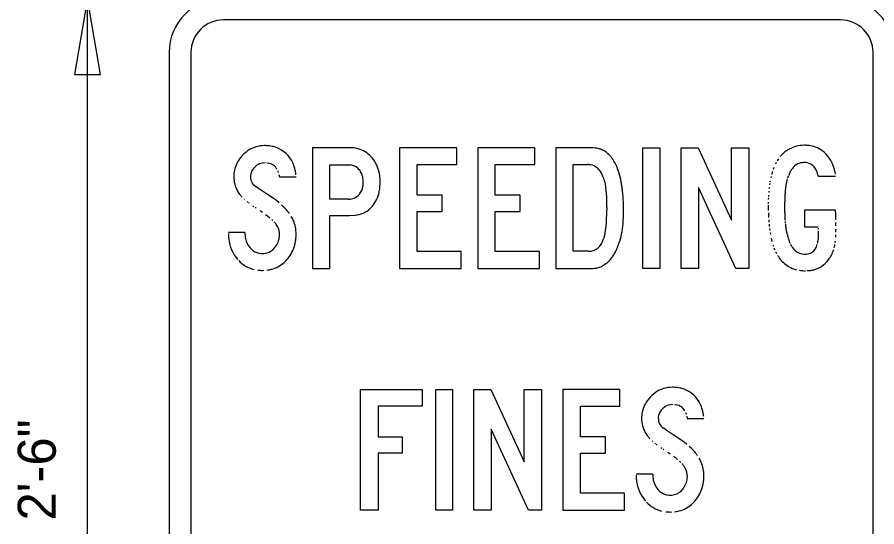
# Model space of a CAD drawing. Extents: x 0 to 770, y 0 to 495.
# Drawn here: x 242 to 321.1, y 84.8 to 131.8 of the extents above; entities that cross this region are included whole.
import ezdxf

# ---------------------------------------------------------------- set-up
doc = ezdxf.new("R2010")
doc.units = 0
for name, color, linetype in [('Default', 7, 'Continuous'), ('Dimension', 7, 'Continuous'), ('GSBWFill', 7, 'Continuous'), ('GSDims', 7, 'Continuous'), ('TextStructures', 7, 'Continuous')]:
    doc.layers.add(name, color=color, linetype=linetype)

msp = doc.modelspace()

# ---------------------------------------------------------------- linework, layer by layer
at = {"layer": 'Default'}
for p, q in [((269.223, 119.747), (269.223, 108.62)), ((273.034, 119.722), (273.034, 119.721)), ((273.42, 119.643), (273.42, 119.644)), ((282.487, 119.747), (277.234, 119.747)), ((277.234, 119.747), (277.234, 108.62)), ((282.487, 118.19), (282.487, 119.747)), ((289.675, 119.747), (284.423, 119.747)), ((284.423, 119.747), (284.423, 108.62)), ((289.675, 118.19), (289.675, 119.747)), ((294.627, 119.747), (291.612, 119.747)), ((291.612, 119.747), (291.612, 108.62)), ((295.67, 119.622), (295.67, 119.622)), ((295.969, 119.498), (295.969, 119.498)), ((299.623, 119.747), (301.181, 119.747)), ((299.623, 108.62), (299.623, 119.747)), ((301.181, 119.747), (301.181, 108.62)), ((303.14, 108.62), (303.14, 119.747)), ((303.14, 119.747), (304.709, 119.747)), ((304.709, 119.747), (307.769, 113.071)), ((307.769, 113.071), (307.769, 119.747)), ((307.769, 119.747), (309.371, 119.747)), ((309.371, 119.747), (309.371, 108.62)), ((274.608, 118.914), (274.608, 118.914)), ((296.485, 119.113), (296.485, 119.113)), ((296.692, 118.885), (296.692, 118.885)), ((296.953, 118.511), (296.845, 118.679)), ((265, 118.34), (265.142, 118.323)), ((270.814, 115.018), (270.814, 118.178)), ((270.814, 118.178), (272.427, 118.178)), ((272.427, 118.178), (272.706, 118.16)), ((278.848, 115.385), (278.848, 118.19)), ((278.848, 118.19), (282.487, 118.19)), ((286.037, 115.385), (286.037, 118.19)), ((286.037, 118.19), (289.675, 118.19)), ((293.203, 110.211), (293.203, 118.19)), ((293.203, 118.19), (294.516, 118.19)), ((294.516, 118.19), (294.516, 118.19)), ((294.666, 118.183), (294.666, 118.183)), ((295.258, 117.995), (295.258, 117.995)), ((297.054, 118.33), (297.054, 118.33)), ((297.119, 118.203), (297.119, 118.203)), ((297.18, 118.071), (297.18, 118.071)), ((297.239, 117.934), (297.239, 117.934)), ((266.012, 117.619), (266.072, 117.455)), ((266.126, 117.27), (266.174, 117.066)), ((266.174, 117.066), (267.709, 117.066)), ((273.523, 117.722), (273.523, 117.722)), ((273.744, 117.341), (273.744, 117.341)), ((275.324, 117.602), (275.324, 117.602)), ((275.39, 117.29), (275.39, 117.29)), ((295.577, 117.724), (295.577, 117.724)), ((295.714, 117.546), (295.714, 117.546)), ((295.797, 117.411), (295.797, 117.411)), ((295.872, 117.262), (295.873, 117.262)), ((295.942, 117.102), (295.942, 117.102)), ((297.349, 117.643), (297.295, 117.791)), ((297.399, 117.49), (297.399, 117.49)), ((297.447, 117.331), (297.447, 117.331)), ((311.412, 117.086), (311.389, 116.985)), ((312.981, 117.053), (313.011, 117.143)), ((315.748, 117.121), (317.35, 117.121)), ((315.748, 117.121), (315.748, 117.121)), ((317.295, 117.497), (317.256, 117.676)), ((317.326, 117.312), (317.295, 117.497)), ((273.834, 117.043), (273.834, 117.043)), ((273.885, 116.532), (273.885, 116.532)), ((275.4, 115.946), (275.443, 116.621)), ((275.43, 116.963), (275.43, 116.963)), ((296.153, 116.314), (296.172, 116.19)), ((311.29, 116.451), (311.273, 116.339)), ((311.326, 116.67), (311.307, 116.561)), ((312.785, 116.105), (312.837, 116.459)), ((312.837, 116.459), (312.899, 116.765)), ((312.899, 116.765), (312.924, 116.865)), ((312.952, 116.961), (312.981, 117.053)), ((264.237, 115.997), (264.012, 116.17)), ((264.435, 115.856), (264.237, 115.997)), ((264.605, 115.742), (264.435, 115.856)), ((264.973, 115.512), (264.605, 115.742)), ((265.311, 115.291), (264.973, 115.512)), ((273.856, 116.186), (273.856, 116.186)), ((275.225, 115.208), (275.311, 115.489)), ((296.172, 116.19), (296.19, 116.059)), ((296.222, 115.775), (296.235, 115.622)), ((308.158, 108.62), (304.731, 116.075)), ((304.731, 116.075), (304.731, 108.62)), ((311.205, 115.751), (311.195, 115.628)), ((311.243, 116.109), (311.229, 115.991)), ((312.719, 115.368), (312.743, 115.703)), ((312.743, 115.703), (312.785, 116.105)), ((262.93, 115.001), (262.974, 114.964)), ((263.192, 114.793), (263.257, 114.745)), ((263.327, 114.693), (263.4, 114.64)), ((265.619, 115.078), (265.311, 115.291)), ((265.895, 114.874), (265.619, 115.078)), ((266.143, 114.678), (265.895, 114.874)), ((273.042, 115.108), (273.042, 115.108)), ((273.529, 115.474), (273.529, 115.474)), ((274.838, 114.478), (275.118, 114.946)), ((281.151, 115.385), (278.848, 115.385)), ((281.151, 113.872), (281.151, 115.385)), ((288.34, 115.385), (286.037, 115.385)), ((288.34, 113.872), (288.34, 115.385)), ((296.257, 115.294), (296.265, 115.12)), ((296.278, 114.749), (296.282, 114.553)), ((297.802, 115.128), (297.794, 115.239)), ((297.821, 114.789), (297.815, 114.904)), ((311.154, 114.716), (311.152, 114.579)), ((311.165, 115.118), (311.16, 114.986)), ((311.178, 115.376), (311.171, 115.248)), ((312.691, 114.614), (312.701, 115.006)), ((312.701, 115.006), (312.719, 115.368)), ((263.737, 114.401), (263.832, 114.335)), ((263.932, 114.266), (264.035, 114.196)), ((264.371, 113.969), (264.491, 113.888)), ((266.555, 114.316), (266.363, 114.492)), ((296.282, 114.553), (296.284, 114.35)), ((311.152, 114.44), (311.153, 114.204)), ((311.153, 114.204), (311.157, 113.974)), ((312.687, 114.195), (312.691, 114.614)), ((312.688, 114.092), (312.687, 114.195)), ((312.689, 113.99), (312.688, 114.092)), ((312.69, 113.889), (312.689, 113.99)), ((317.35, 114.006), (314.501, 114.006)), ((314.501, 114.006), (314.501, 112.448)), ((317.364, 113.671), (317.35, 114.006)), ((264.491, 113.888), (264.616, 113.805)), ((264.905, 113.594), (265.083, 113.458)), ((265.083, 113.458), (265.283, 113.293)), ((265.467, 113.143), (265.577, 113.039)), ((270.814, 108.62), (270.814, 113.494)), ((270.814, 113.494), (272.612, 113.494)), ((272.612, 113.494), (273.172, 113.533)), ((273.43, 113.581), (273.43, 113.581)), ((273.79, 113.691), (273.79, 113.691)), ((278.848, 110.2), (278.848, 113.872)), ((278.848, 113.872), (281.151, 113.872)), ((286.037, 110.2), (286.037, 113.872)), ((286.037, 113.872), (288.34, 113.872)), ((296.268, 113.577), (296.25, 113.253)), ((296.281, 113.871), (296.268, 113.577)), ((297.816, 113.024), (297.831, 113.286)), ((297.831, 113.286), (297.84, 113.554)), ((297.84, 113.554), (297.843, 113.828)), ((311.162, 113.749), (311.171, 113.529)), ((311.171, 113.529), (311.181, 113.314)), ((312.692, 113.79), (312.69, 113.889)), ((312.694, 113.692), (312.692, 113.79)), ((312.697, 113.595), (312.694, 113.692)), ((312.7, 113.5), (312.697, 113.595)), ((312.704, 113.406), (312.7, 113.5)), ((312.709, 113.313), (312.704, 113.406)), ((312.714, 113.221), (312.709, 113.313)), ((312.72, 113.131), (312.714, 113.221)), ((312.726, 113.042), (312.72, 113.131)), ((317.375, 113.369), (317.364, 113.671)), ((317.381, 113.098), (317.375, 113.369)), ((296.196, 112.504), (296.155, 112.156)), ((297.737, 112.272), (297.769, 112.517)), ((311.194, 113.103), (311.21, 112.898)), ((311.228, 112.697), (311.248, 112.501)), ((312.739, 112.867), (312.732, 112.954)), ((312.747, 112.782), (312.739, 112.867)), ((312.764, 112.615), (312.756, 112.698)), ((312.774, 112.533), (312.764, 112.615)), ((312.784, 112.453), (312.774, 112.533)), ((312.794, 112.374), (312.784, 112.453)), ((312.805, 112.296), (312.794, 112.374)), ((314.501, 112.448), (315.748, 112.448)), ((315.756, 112.342), (315.759, 112.247)), ((317.382, 112.542), (317.383, 112.859)), ((263.002, 111.936), (261.478, 111.936)), ((261.478, 111.836), (261.48, 111.673)), ((263.002, 111.936), (263.002, 111.936)), ((296.051, 111.576), (295.988, 111.342)), ((296.107, 111.847), (296.051, 111.576)), ((296.155, 112.156), (296.107, 111.847)), ((297.548, 111.351), (297.604, 111.573)), ((297.604, 111.573), (297.654, 111.8)), ((297.654, 111.8), (297.698, 112.033)), ((297.698, 112.033), (297.737, 112.272)), ((311.27, 112.31), (311.295, 112.124)), ((311.323, 111.943), (311.352, 111.767)), ((312.816, 112.22), (312.805, 112.296)), ((312.828, 112.144), (312.816, 112.22)), ((312.841, 112.07), (312.828, 112.144)), ((312.854, 111.998), (312.841, 112.07)), ((312.867, 111.926), (312.854, 111.998)), ((312.882, 111.856), (312.867, 111.926)), ((312.896, 111.787), (312.882, 111.856)), ((312.911, 111.72), (312.896, 111.787)), ((315.744, 111.536), (315.732, 111.377)), ((315.752, 111.707), (315.744, 111.536)), ((315.757, 111.888), (315.752, 111.707)), ((315.759, 112.08), (315.757, 111.888)), ((317.356, 111.507), (317.366, 111.731)), ((317.373, 111.977), (317.379, 112.248)), ((295.781, 110.874), (295.781, 110.874)), ((295.875, 111.05), (295.875, 111.05)), ((297.418, 110.925), (297.418, 110.925)), ((311.419, 111.429), (311.455, 111.268)), ((311.455, 111.268), (311.495, 111.111)), ((311.58, 110.812), (311.626, 110.671)), ((315.699, 111.092), (315.677, 110.967)), ((315.717, 111.229), (315.699, 111.092)), ((315.732, 111.377), (315.717, 111.229)), ((317.272, 110.734), (317.293, 110.843)), ((317.312, 110.975), (317.329, 111.13)), ((282.91, 110.2), (278.848, 110.2)), ((282.91, 108.62), (282.91, 110.2)), ((290.098, 110.2), (286.037, 110.2)), ((290.098, 108.62), (290.098, 110.2)), ((294.949, 110.252), (294.949, 110.252)), ((296.983, 109.955), (296.983, 109.955)), ((297.081, 110.133), (297.081, 110.133)), ((297.22, 110.421), (297.22, 110.421)), ((317.226, 110.543), (317.272, 110.734)), ((296.477, 109.292), (296.477, 109.292)), ((296.657, 109.488), (296.77, 109.633)), ((296.879, 109.789), (296.879, 109.789)), ((264.605, 108.453), (264.743, 108.455)), ((269.223, 108.62), (270.814, 108.62)), ((277.234, 108.62), (282.91, 108.62)), ((284.423, 108.62), (290.098, 108.62)), ((296.221, 109.07), (296.221, 109.07)), ((301.181, 108.62), (299.623, 108.62)), ((304.731, 108.62), (303.14, 108.62)), ((309.371, 108.62), (308.158, 108.62)), ((273.629, 97.492), (279.304, 97.492)), ((273.629, 86.364), (273.629, 97.492)), ((279.304, 97.492), (279.304, 95.934)), ((280.551, 97.492), (282.108, 97.492)), ((280.551, 86.364), (280.551, 97.492)), ((282.108, 97.492), (282.108, 86.364)), ((284.067, 86.364), (284.067, 97.492)), ((284.067, 97.492), (285.636, 97.492)), ((285.636, 97.492), (288.696, 90.815)), ((288.696, 90.815), (288.696, 97.492)), ((288.696, 97.492), (290.298, 97.492)), ((290.298, 97.492), (290.298, 86.364)), ((297.509, 97.492), (292.257, 97.492)), ((292.257, 97.492), (292.257, 86.364)), ((297.509, 95.934), (297.509, 97.492)), ((279.304, 95.934), (275.254, 95.934)), ((275.254, 95.934), (275.254, 93.13)), ((293.87, 93.13), (293.87, 95.934)), ((293.87, 95.934), (297.509, 95.934)), ((302.523, 96.084), (302.665, 96.068)), ((303.535, 95.364), (303.595, 95.2)), ((303.649, 95.015), (303.696, 94.81)), ((303.696, 94.81), (305.232, 94.81)), ((289.086, 86.364), (285.658, 93.82)), ((285.658, 93.82), (285.658, 86.364)), ((301.76, 93.742), (301.535, 93.914)), ((301.958, 93.6), (301.76, 93.742)), ((302.127, 93.486), (301.958, 93.6)), ((302.496, 93.257), (302.127, 93.486)), ((275.254, 93.13), (277.468, 93.13)), ((277.468, 93.13), (277.468, 91.617)), ((296.174, 93.13), (293.87, 93.13)), ((296.174, 91.617), (296.174, 93.13)), ((300.453, 92.746), (300.497, 92.709)), ((302.834, 93.035), (302.496, 93.257)), ((303.141, 92.823), (302.834, 93.035)), ((303.418, 92.618), (303.141, 92.823)), ((303.666, 92.423), (303.418, 92.618)), ((300.715, 92.538), (300.78, 92.489)), ((300.849, 92.438), (300.923, 92.384)), ((301.26, 92.145), (301.355, 92.079)), ((301.454, 92.011), (301.557, 91.94)), ((304.077, 92.061), (303.885, 92.237)), ((277.468, 91.617), (275.254, 91.617)), ((275.254, 91.617), (275.254, 86.364)), ((293.87, 87.944), (293.87, 91.617)), ((293.87, 91.617), (296.174, 91.617)), ((301.893, 91.713), (302.014, 91.633)), ((302.014, 91.633), (302.138, 91.55)), ((302.428, 91.338), (302.606, 91.202)), ((302.606, 91.202), (302.806, 91.038)), ((302.99, 90.888), (303.099, 90.783)), ((300.525, 89.68), (299, 89.68)), ((299, 89.58), (299.003, 89.418)), ((300.525, 89.68), (300.525, 89.68)), ((297.932, 87.944), (293.87, 87.944)), ((297.932, 86.364), (297.932, 87.944)), ((275.254, 86.364), (273.629, 86.364)), ((282.108, 86.364), (280.551, 86.364)), ((285.658, 86.364), (284.067, 86.364)), ((290.298, 86.364), (289.086, 86.364)), ((292.257, 86.364), (297.932, 86.364)), ((302.127, 86.197), (302.266, 86.2))]:
    msp.add_line(p, q, dxfattribs=at)
for points in [[(272.621, 119.747), (272.621, 119.747), (269.223, 119.747)], [(295.025, 119.734), (294.832, 119.744), (294.627, 119.747)], [(295.373, 119.692), (295.205, 119.716), (295.025, 119.734)], [(295.67, 119.622), (295.528, 119.66), (295.373, 119.692)], [(297.535, 116.998), (297.514, 117.084), (297.493, 117.168)], [(296.033, 116.836), (296.033, 116.836), (296.06, 116.741)], [(296.06, 116.741), (296.085, 116.643), (296.109, 116.54)], [(296.109, 116.54), (296.132, 116.431), (296.153, 116.314)], [(297.575, 116.824), (297.555, 116.912), (297.535, 116.998)], [(297.629, 116.552), (297.612, 116.644), (297.575, 116.824)], [(297.662, 116.365), (297.646, 116.459), (297.629, 116.552)], [(297.692, 116.172), (297.677, 116.269), (297.662, 116.365)], [(296.19, 116.059), (296.207, 115.92), (296.222, 115.775)], [(296.235, 115.622), (296.247, 115.462), (296.257, 115.294)], [(297.72, 115.974), (297.706, 116.074), (297.692, 116.172)], [(297.744, 115.77), (297.732, 115.873), (297.72, 115.974)], [(297.766, 115.562), (297.755, 115.667), (297.744, 115.77)], [(297.794, 115.239), (297.785, 115.348), (297.766, 115.562)], [(272.539, 115.018), (272.539, 115.018), (270.814, 115.018)], [(296.265, 115.12), (296.273, 114.938), (296.278, 114.749)], [(297.815, 114.904), (297.809, 115.017), (297.802, 115.128)], [(297.831, 114.557), (297.826, 114.674), (297.821, 114.789)], [(296.284, 114.35), (296.285, 114.139), (296.281, 113.871)], [(297.837, 114.319), (297.834, 114.438), (297.831, 114.557)], [(297.842, 114.076), (297.84, 114.198), (297.837, 114.319)], [(297.843, 113.828), (297.843, 113.952), (297.842, 114.076)], [(296.25, 113.253), (296.23, 112.893), (296.196, 112.504)], [(297.769, 112.517), (297.796, 112.767), (297.816, 113.024)], [(297.418, 110.925), (297.486, 111.135), (297.548, 111.351)], [(294.571, 110.211), (294.571, 110.211), (293.203, 110.211)], [(291.612, 108.62), (294.827, 108.62), (295.002, 108.625)]]:
    msp.add_lwpolyline(points, dxfattribs=at)
for centre, radius, start, end in [((265.123, 116.823), 3.23, 125.4418, 141.2252), ((264.771, 117.297), 2.64, 89.2737, 125.1802), ((264.81, 116.188), 3.748, 83.339, 90.0746), ((264.87, 116.751), 3.182, 78.2121, 83.2376), ((264.941, 117.089), 2.837, 70.1046, 78.2264), ((264.992, 117.29), 2.63, 24.1049, 69.6601), ((272.625, 116.52), 3.227, 82.7267, 90.0706), ((272.678, 116.961), 2.784, 74.5351, 82.6474), ((272.74, 117.204), 2.532, 42.4587, 74.4236), ((295.229, 118.143), 1.544, 61.363, 73.3883), ((294.842, 117.45), 2.337, 45.3467, 61.1731), ((314.219, 117.347), 2.525, 121.8461, 132.9879), ((314.684, 116.681), 3.337, 115.972, 122.5995), ((314.512, 117.035), 2.943, 105.1938, 115.983), ((314.454, 117.227), 2.743, 89.949, 105.0722), ((314.461, 116.569), 3.401, 82.5188, 90.0791), ((314.517, 117.032), 2.935, 76.8308, 82.4098), ((314.594, 117.343), 2.615, 61.861, 76.9248), ((314.572, 117.331), 2.635, 43.5425, 61.5587), ((264.727, 117.101), 2.747, 140.5703, 168.2275), ((272.393, 116.855), 3.024, 14.2957, 42.9079), ((294.587, 117.181), 2.708, 39.0029, 45.5205), ((294.297, 116.943), 3.083, 34.2627, 39.0379), ((314.908, 116.772), 3.426, 145.0163, 149.0349), ((314.398, 117.158), 2.786, 133.0243, 140.7189), ((314.348, 117.111), 2.95, 24.4959, 43.6518), ((264.723, 117.076), 1.211, 132.6297, 202.1565), ((264.816, 117.056), 1.29, 88.5422, 135.0606), ((265.028, 117.302), 1.028, 26.6666, 83.6019), ((264.541, 117.036), 3.147, 16.2411, 24.9806), ((264.088, 116.898), 3.62, 11.0316, 16.3233), ((272.589, 116.96), 1.206, 39.2074, 84.4146), ((294.517, 116.47), 1.72, 85.0409, 90.052), ((294.566, 116.842), 1.345, 59.0008, 85.7331), ((294.538, 116.822), 1.376, 40.9656, 58.4431), ((293.693, 116.554), 3.801, 27.8491, 30.9695), ((293.355, 116.374), 4.184, 25.9265, 27.8738), ((293.066, 116.233), 4.506, 24.0732, 25.9267), ((292.744, 116.089), 4.859, 22.3109, 24.0735), ((292.388, 115.943), 5.244, 20.636, 22.3112), ((316.462, 116.022), 5.155, 158.4219, 160.466), ((315.428, 116.475), 4.025, 151.5644, 153.975), ((314.739, 116.776), 1.731, 138.496, 145.831), ((314.43, 117.076), 1.301, 106.6757, 139.3493), ((314.458, 116.934), 1.445, 89.5988, 106.1115), ((314.47, 116.846), 1.533, 84.3521, 90.0781), ((314.533, 117.267), 1.107, 53.1586, 85.4356), ((314.486, 117.233), 1.163, 35.156, 52.3499), ((314.201, 117.029), 1.514, 26.6079, 35.2343), ((314, 116.942), 3.336, 18.7846, 24.6542), ((313.634, 116.818), 3.723, 13.3229, 18.7785), ((264.916, 117.074), 2.938, 168.4628, 180.1612), ((264.6, 117.043), 2.622, 179.5181, 209.0783), ((263.592, 116.802), 4.125, 6.1794, 11.0296), ((272.311, 116.767), 1.543, 21.8218, 38.2319), ((272.057, 116.666), 1.817, 11.9834, 21.8077), ((271.947, 116.722), 3.49, 9.3702, 14.6018), ((271.582, 116.662), 3.859, 4.4743, 9.366), ((294.28, 116.591), 1.723, 33.6642, 41.1482), ((294.04, 116.43), 2.011, 29.1747, 33.6892), ((293.763, 116.275), 2.329, 25.0813, 29.1759), ((293.412, 116.111), 2.717, 21.3891, 25.0837), ((292.813, 115.881), 3.358, 16.5148, 21.3058), ((291.566, 115.647), 6.118, 17.5334, 19.0451), ((291.097, 115.499), 6.61, 16.0981, 17.5338), ((290.587, 115.351), 7.14, 14.7347, 16.0984), ((317.558, 115.661), 6.309, 162.4213, 165.0947), ((316.111, 116.056), 3.285, 157.4853, 160.6635), ((315.668, 116.239), 2.806, 153.9576, 157.4883), ((315.307, 116.416), 2.404, 150.0465, 153.9602), ((315.02, 116.581), 2.073, 145.7282, 150.0482), ((313.901, 116.878), 1.85, 21.5964, 26.6481), ((313.548, 116.738), 2.229, 17.1396, 21.6006), ((312.921, 116.551), 2.884, 11.4154, 17.022), ((264.486, 117.013), 0.968, 204.0171, 240.6614), ((271.4, 116.543), 2.485, 359.7377, 11.6141), ((271.909, 116.524), 1.976, 350.1569, 0.216), ((271.098, 116.624), 4.345, 359.9525, 4.4725), ((264.813, 117.169), 2.869, 209.1955, 217.4851), ((272.396, 116.426), 1.48, 319.9774, 350.6811), ((271.491, 116.468), 3.943, 345.6252, 352.3887), ((265.079, 117.371), 3.203, 217.4723, 222.6179), ((272.557, 116.368), 1.35, 269.234, 291.0673), ((272.605, 116.196), 1.172, 291.8743, 321.9947), ((272.423, 116.204), 2.973, 334.9699, 340.4326), ((263.436, 111.073), 4.5, 39.1273, 46.1255), ((263.807, 111.376), 4.021, 34.7564, 39.1072), ((272.97, 115.874), 2.332, 290.5966, 323.2356), ((264.338, 111.716), 3.389, 22.8402, 30.1431), ((272.715, 116.662), 3.163, 278.3016, 283.0626), ((272.816, 116.246), 2.735, 282.9803, 290.8726), ((264.219, 111.495), 2.048, 35.3865, 43.879), ((264.627, 111.767), 1.558, 5.1973, 35.9416), ((264.539, 111.803), 3.17, 359.7757, 22.7948), ((265.574, 111.822), 4.096, 182.078, 186.51), ((265.512, 111.89), 2.51, 178.9652, 191.6289), ((264.326, 111.733), 1.856, 320.6387, 355.8508), ((264.301, 111.757), 1.884, 355.1863, 4.6054), ((263.389, 111.787), 4.32, 353.6698, 0.0575), ((318.287, 112.958), 5.516, 192.9693, 195.0608), ((264.879, 111.71), 3.393, 185.9642, 221.4144), ((264.955, 111.778), 1.942, 191.6865, 220.534), ((264.228, 111.672), 3.473, 341.545, 348.9423), ((263.914, 111.734), 3.793, 348.9338, 353.5913), ((294.655, 111.513), 1.295, 283.1391, 330.4047), ((294.144, 111.866), 1.914, 328.766, 334.7522), ((293.958, 111.959), 2.122, 334.6275, 343.0977), ((291.622, 112.905), 6.125, 336.0791, 341.1452), ((317.628, 112.782), 4.834, 195.083, 196.6096), ((317.186, 112.651), 4.373, 196.6088, 198.2409), ((316.786, 112.519), 3.952, 198.2401, 199.9862), ((316.426, 112.388), 3.569, 199.9854, 201.8543), ((316.104, 112.259), 3.222, 201.8535, 203.8541), ((315.528, 111.99), 2.586, 205.9842, 209.4497), ((314.291, 111.162), 1.396, 334.8823, 347.1516), ((264.632, 111.496), 1.514, 220.3788, 233.6082), ((264.551, 111.407), 1.394, 234.108, 267.0901), ((264.604, 111.679), 1.669, 265.7463, 283.9893), ((264.651, 111.423), 1.41, 284.674, 322.0204), ((264.481, 111.589), 3.206, 317.9943, 341.5213), ((294.582, 111.859), 1.649, 269.6389, 282.8773), ((293.66, 111.905), 3.853, 326.6728, 329.5939), ((293.286, 112.125), 4.287, 329.5932, 332.3136), ((292.684, 112.436), 4.964, 332.3586, 336.0481), ((316.345, 112.302), 4.994, 200.7366, 203.0596), ((315.611, 111.971), 4.188, 205.5245, 208.1364), ((315.217, 111.815), 2.229, 209.4776, 213.304), ((314.922, 111.621), 1.877, 213.2805, 219.0188), ((314.681, 111.425), 1.565, 219.0003, 227.0806), ((314.457, 111.172), 1.228, 226.6802, 271.0039), ((314.485, 111.608), 1.664, 269.8001, 279.9547), ((314.559, 111.16), 1.21, 280.1681, 292.7446), ((314.629, 110.971), 1.009, 293.1983, 336.5465), ((313.889, 111.402), 3.444, 333.3488, 342.4003), ((264.478, 111.254), 2.79, 222.5722, 256.2694), ((264.599, 111.394), 2.989, 309.4698, 319.257), ((294.725, 111.052), 2.484, 307.0504, 314.8813), ((294.47, 111.309), 2.845, 314.8692, 320.2204), ((293.974, 111.699), 3.477, 323.5454, 326.6732), ((314.998, 111.621), 3.482, 210.8602, 215.3012), ((314.723, 111.425), 3.144, 215.2778, 220.0295), ((314.352, 111.085), 2.641, 219.5613, 248.1223), ((314.586, 111.02), 2.648, 308.9185, 326.5154), ((314.354, 111.177), 2.928, 326.4488, 333.1968), ((264.601, 112.015), 3.563, 263.5163, 270.0562), ((264.654, 111.68), 3.225, 276.3846, 281.0336), ((264.77, 111.194), 2.726, 280.6014, 309.3667), ((294.884, 110.844), 2.221, 273.0466, 307.0255), ((314.414, 111.262), 2.829, 248.2816, 256.7566), ((314.537, 111.909), 3.489, 261.4961, 265.9128), ((314.566, 112.338), 3.919, 265.941, 270.0277), ((314.59, 111.629), 3.209, 272.5644, 278.2534), ((314.647, 111.232), 2.808, 278.2589, 284.4776), ((314.77, 110.811), 2.37, 284.1488, 308.6288), ((302.294, 95.041), 2.64, 89.2737, 125.1802), ((302.332, 93.933), 3.748, 83.339, 90.0746), ((302.392, 94.496), 3.182, 78.2121, 83.2376), ((302.464, 94.834), 2.837, 70.1046, 78.2264), ((302.515, 95.035), 2.63, 24.1049, 69.6601), ((302.25, 94.846), 2.747, 140.5703, 168.2275), ((302.646, 94.568), 3.23, 125.4418, 141.2252), ((302.246, 94.821), 1.211, 132.6297, 202.1565), ((302.339, 94.801), 1.29, 88.5422, 135.0606), ((302.55, 95.046), 1.028, 26.6666, 83.6019), ((302.064, 94.78), 3.147, 16.2411, 24.9806), ((302.439, 94.818), 2.938, 168.4628, 180.1612), ((301.61, 94.643), 3.62, 11.0316, 16.3233), ((301.114, 94.546), 4.125, 6.1794, 11.0296), ((302.122, 94.788), 2.622, 179.5181, 209.0783), ((302.009, 94.758), 0.968, 204.0171, 240.6614), ((302.336, 94.913), 2.869, 209.1955, 217.4851), ((302.601, 95.116), 3.203, 217.4723, 222.6179), ((300.959, 88.817), 4.5, 39.1273, 46.1255), ((301.329, 89.121), 4.021, 34.7564, 39.1072), ((301.861, 89.461), 3.389, 22.8402, 30.1431), ((301.742, 89.24), 2.048, 35.3865, 43.879), ((302.15, 89.512), 1.558, 5.1973, 35.9416), ((302.061, 89.548), 3.17, 359.7757, 22.7948), ((303.097, 89.566), 4.096, 182.078, 186.51), ((303.035, 89.635), 2.51, 178.9652, 191.6289), ((301.824, 89.501), 1.884, 355.1863, 4.6054), ((300.912, 89.531), 4.32, 353.6698, 0.0575), ((302.402, 89.455), 3.393, 185.9642, 221.4144), ((302.478, 89.522), 1.942, 191.6865, 220.534), ((301.849, 89.478), 1.856, 320.6387, 355.8508), ((301.75, 89.416), 3.473, 341.545, 348.9423), ((301.436, 89.478), 3.793, 348.9338, 353.5913), ((302.155, 89.241), 1.514, 220.3788, 233.6082), ((302.074, 89.152), 1.394, 234.108, 267.0901), ((302.127, 89.424), 1.669, 265.7463, 283.9893), ((302.173, 89.168), 1.41, 284.674, 322.0204), ((302.004, 89.333), 3.206, 317.9943, 341.5213), ((302.001, 88.999), 2.79, 222.5722, 256.2694), ((302.122, 89.138), 2.989, 309.4698, 319.257), ((302.124, 89.76), 3.563, 263.5163, 270.0562), ((302.177, 89.425), 3.225, 276.3846, 281.0336), ((302.293, 88.938), 2.726, 280.6014, 309.3667)]:
    msp.add_arc(centre, radius, start, end, dxfattribs=at)
at = {"layer": 'Dimension'}
msp.add_lwpolyline([(248.518, 133.518), (247.329, 126.501), (249.706, 126.501)], close=True, dxfattribs=at)
at = {"layer": 'GSBWFill'}
for p, q in [((317.795, 131.518), (261.029, 131.518)), ((256.029, 128.518), (256.029, 55.06)), ((258.029, 128.518), (258.029, 55.06)), ((320.795, 55.06), (320.795, 128.518))]:
    msp.add_line(p, q, dxfattribs=at)
for centre, radius, start, end in [((261.029, 128.518), 5, 90, 180), ((317.795, 128.518), 5, 0, 90), ((261.029, 128.518), 3, 90, 180), ((317.795, 128.518), 3, 0, 90)]:
    msp.add_arc(centre, radius, start, end, dxfattribs=at)
at = {"layer": 'GSDims'}
msp.add_line((248.518, 50.06), (248.518, 133.518), dxfattribs=at)

# ---------------------------------------------------------------- texts
at = {"layer": 'TextStructures'}
msp.add_text('2\'-6"', height=3.5, rotation=90, dxfattribs=at).set_placement((245.596, 85.414))

doc.saveas('drawing.dxf')
